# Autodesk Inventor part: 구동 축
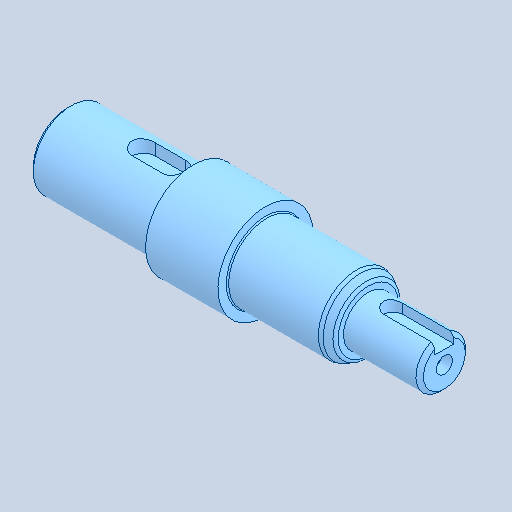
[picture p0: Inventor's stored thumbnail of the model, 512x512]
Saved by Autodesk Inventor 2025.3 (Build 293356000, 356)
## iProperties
Created: 2025-09
Part Number: 구동 축
Material: 강철, 탄소
Document SubType Name: Modeling
Designer: PC-15
Density: 7.85 g/cm^3
Appearance: 기본값
Author: jhkim
Sending System: Autodesk Inventor 2026
Preprocessor: ST-DEVELOPER v20.1
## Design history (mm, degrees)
feature "솔리드1"
node "솔리드2"
